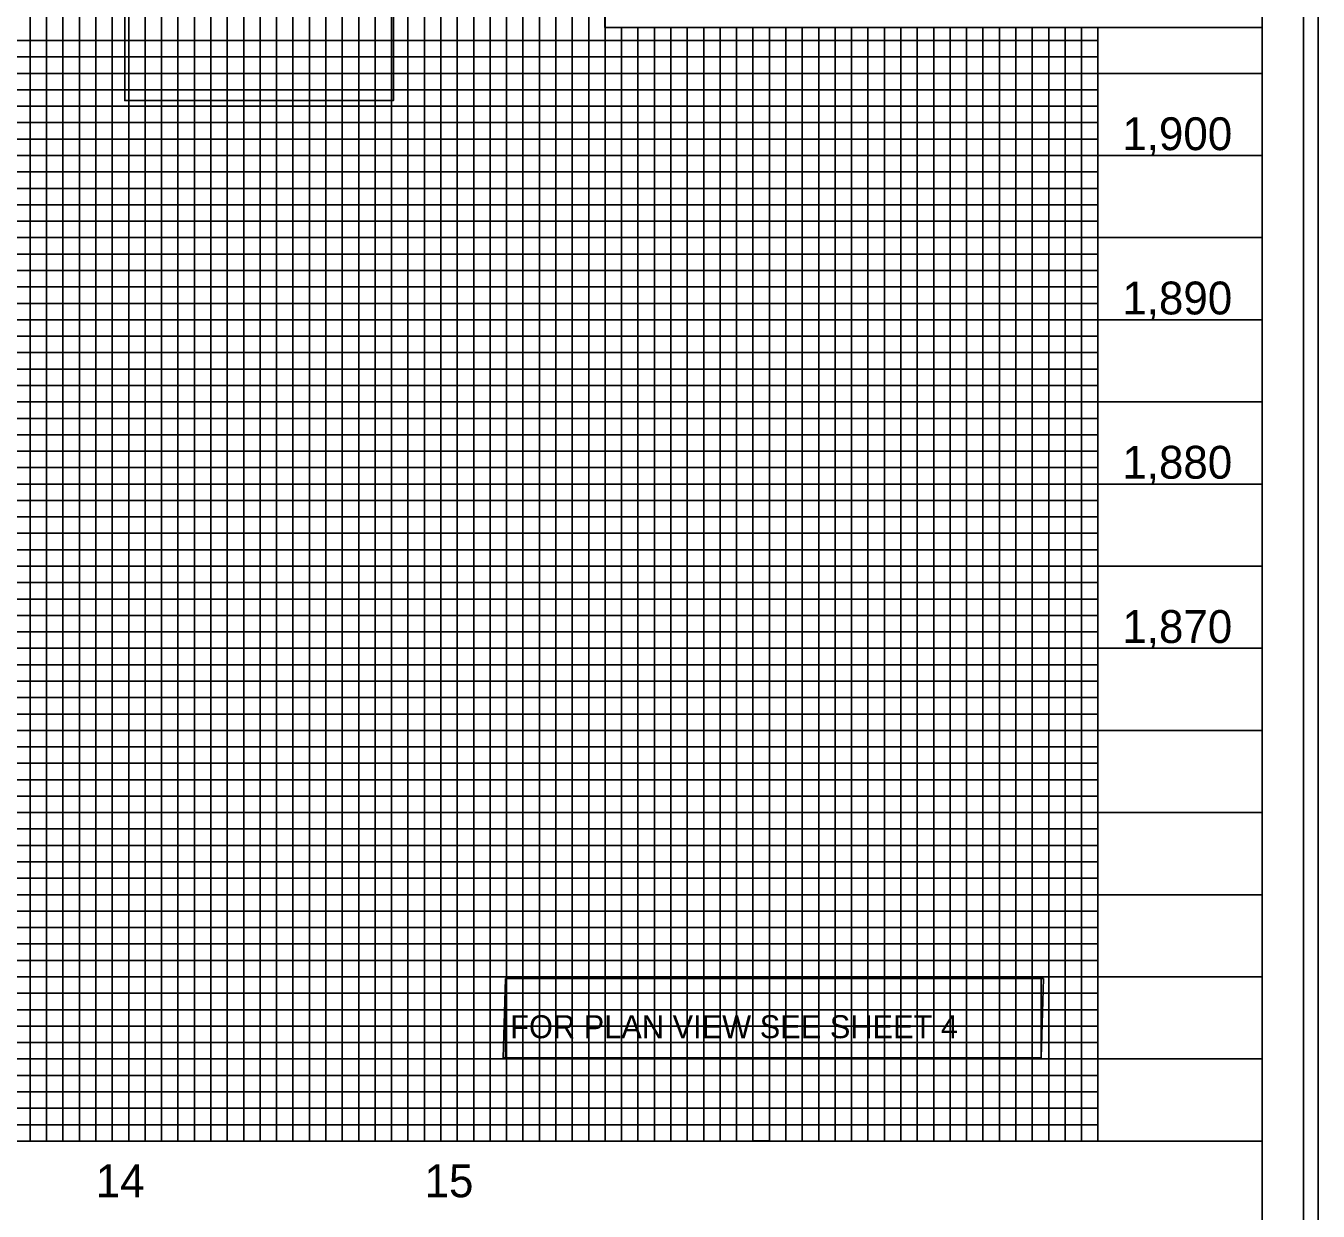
# Model space of a CAD drawing. Extents: x 557032 to 558840, y 515971 to 517218.
# Drawn here: x 558323.1 to 558716.5, y 516671.8 to 517032.6 of the extents above; entities that cross this region are included whole.
import ezdxf

# ---------------------------------------------------------------- set-up
doc = ezdxf.new("R2010")
doc.units = 0
for name, color, linetype in [('Exist Vertical Profile Horizontal Axis Label Major', 7, 'Continuous'), ('Exist Vertical Profile Vertical Axis Label', 7, 'Continuous'), ('Prop Vertical Profile Grade Label', 7, 'Continuous'), ('Prop VPI Label', 7, 'Continuous'), ('Scratch_Level_5', 7, 'Continuous'), ('Sheet DOT Grid CELL', 7, 'Continuous'), ('Sheet Layout Profile Border Port 1', 7, 'Continuous'), ('Sheet Plot Border Inside CELL', 7, 'Continuous'), ('Sheet Plot Border Outside CELL', 7, 'Continuous'), ('Sheet Profile CELL', 7, 'Continuous'), ('Sheet Profile Grid Major CELL', 7, 'Continuous'), ('Sheet Profile Grid Middle CELL', 7, 'Continuous'), ('Sheet Profile Grid Minor CELL', 7, 'Continuous'), ('Sheet Sticker Exception Certification CELL', 7, 'Continuous')]:
    doc.layers.add(name, color=color, linetype=linetype)

msp = doc.modelspace()

# ---------------------------------------------------------------- linework, layer by layer
at = {"layer": 'Prop Vertical Profile Grade Label'}
msp.add_lwpolyline([(558353.25, 517063.44), (558435.01, 517063.44), (558435.01, 517009.9), (558353.25, 517009.9)], close=True, dxfattribs=at)
at = {"layer": 'Prop VPI Label'}
for points in [[(558469.16, 516742.65), (558632.86, 516742.65), (558632.14, 516718.54), (558468.44, 516718.54)], [(558469.16, 516742.65), (558632.14, 516742.65), (558632.14, 516718.54), (558469.16, 516718.54)]]:
    msp.add_lwpolyline(points, close=True, dxfattribs=at)
at = {"layer": 'Scratch_Level_5'}
msp.add_lwpolyline([(558499.45, 517193.17), (558099.45, 517193.17), (558099.45, 516693.17), (558649.45, 516693.17), (558649.45, 517032.12), (558499.45, 517032.12)], close=True, dxfattribs=at)
at = {"layer": 'Sheet DOT Grid CELL'}
for p, q in [((558349.45, 516693.17), (558349.45, 517193.17)), ((558399.45, 516693.17), (558399.45, 517193.17)), ((558449.45, 516693.17), (558449.45, 517193.17)), ((558499.45, 516693.17), (558499.45, 517055.62)), ((558549.45, 516693.17), (558549.45, 517032.12)), ((558599.45, 516693.17), (558599.45, 517032.12)), ((558649.45, 516693.17), (558649.45, 517032.12)), ((558699.45, 516993.17), (557199.45, 516993.17)), ((558699.45, 516943.17), (557199.45, 516943.17)), ((558699.45, 516893.17), (557199.45, 516893.17)), ((558699.45, 516843.17), (557199.45, 516843.17)), ((558699.45, 516793.17), (557199.45, 516793.17)), ((558699.45, 516743.17), (557199.45, 516743.17))]:
    msp.add_line(p, q, dxfattribs=at)
at = {"layer": 'Sheet Layout Profile Border Port 1'}
msp.add_lwpolyline([(557249.45, 517032.12), (557249.45, 516693.17), (558649.45, 516693.17), (558649.45, 517032.12)], dxfattribs=at)
at = {"layer": 'Sheet Plot Border Inside CELL'}
msp.add_lwpolyline([(557045.45, 516140.62), (558711.95, 516140.62), (558711.95, 517195.72), (557045.45, 517195.72)], close=True, dxfattribs=at)
at = {"layer": 'Sheet Plot Border Outside CELL'}
msp.add_lwpolyline([(557032.45, 516118.17), (558716.45, 516118.17), (558716.45, 517218.17), (557032.45, 517218.17)], close=True, dxfattribs=at)
at = {"layer": 'Sheet Profile CELL'}
msp.add_line((557199.45, 516693.17), (558699.45, 516693.17), dxfattribs=at)
msp.add_lwpolyline([(558699.45, 517193.17), (557199.45, 517193.17), (557199.45, 516143.17), (558699.45, 516143.17)], close=True, dxfattribs=at)
at = {"layer": 'Sheet Profile Grid Major CELL'}
for points in [[(557999.45, 517193.17), (558049.45, 517193.17), (558049.45, 516842.99), (558099.45, 516842.99), (558099.45, 517193.17), (558149.45, 517193.17), (558149.45, 516693.17), (558199.45, 516693.17), (558199.45, 517193.17), (558249.45, 517193.17), (558249.45, 516693.17), (558299.45, 516693.17), (558299.45, 517193.17), (558349.45, 517193.17), (558349.45, 516693.17), (558399.45, 516693.17), (558399.45, 517193.17), (558449.45, 517193.17), (558449.45, 516693.17), (558499.45, 516693.17), (558499.45, 517193.17), (558525.75, 517193.17)], [(558649.45, 517032.12), (558649.45, 516693.17), (558699.45, 516693.17), (558699.45, 517043.17)], [(558549.45, 517032.12), (558549.45, 516693.17), (558599.45, 516693.17), (558599.45, 516693.17), (558599.45, 517032.12)], [(558699.45, 516993.17), (557199.45, 516993.17), (557199.45, 516943.17), (558699.45, 516943.17)], [(558699.45, 516893.17), (557199.45, 516893.17), (557199.45, 516843.17), (558699.45, 516843.17)], [(558699.45, 516793.17), (557199.45, 516793.17), (557199.45, 516793.17), (557199.45, 516743.17), (558699.45, 516743.17)]]:
    msp.add_lwpolyline(points, dxfattribs=at)
at = {"layer": 'Sheet Profile Grid Middle CELL'}
for points in [[(558024.45, 517193.17), (558074.45, 517193.17), (558074.45, 516693.17), (558124.45, 516693.17), (558124.45, 517193.17), (558174.45, 517193.17), (558174.45, 516693.17), (558224.45, 516693.17), (558224.45, 517193.17), (558274.45, 517193.17), (558274.45, 516693.17), (558324.45, 516693.17), (558324.45, 517193.17), (558374.45, 517193.17), (558374.45, 516693.17), (558424.45, 516693.17), (558424.45, 517193.17), (558474.45, 517193.17), (558474.45, 516693.17), (558524.45, 516693.17), (558524.45, 517032.12)], [(558524.45, 516955.97), (558524.45, 516693.17), (558574.45, 516693.17), (558574.45, 517032.12)], [(558574.45, 516955.97), (558574.45, 516693.17), (558624.45, 516693.17), (558624.45, 517032.12)], [(558699.45, 517018.17), (557199.45, 517018.17), (557199.45, 516968.17), (558524.45, 516968.17)], [(558524.45, 516968.17), (558699.45, 516968.17)], [(558699.45, 516918.17), (557199.45, 516918.17), (557199.45, 516868.17), (558699.45, 516868.17)], [(558699.45, 516818.17), (557199.45, 516818.17), (557199.45, 516768.17), (558699.45, 516768.17)], [(558699.45, 516718.17), (557199.45, 516718.17)]]:
    msp.add_lwpolyline(points, dxfattribs=at)
at = {"layer": 'Sheet Profile Grid Minor CELL'}
for p, q in [((557249.45, 517028.17), (558649.45, 517028.17)), ((558649.45, 517008.17), (557249.45, 517008.17)), ((557249.45, 517003.17), (558649.45, 517003.17)), ((558649.45, 516983.17), (557249.45, 516983.17)), ((557249.45, 516978.17), (558649.45, 516978.17)), ((558649.45, 516958.17), (557249.45, 516958.17)), ((557249.45, 516953.17), (558649.45, 516953.17)), ((558649.45, 516948.17), (557249.45, 516948.17)), ((557249.45, 516938.17), (558649.45, 516938.17)), ((558649.45, 516933.17), (557249.45, 516933.17)), ((557249.45, 516928.17), (558649.45, 516928.17)), ((558649.45, 516923.17), (557249.45, 516923.17)), ((557249.45, 516913.17), (558649.45, 516913.17)), ((558649.45, 516908.17), (557249.45, 516908.17)), ((557249.45, 516903.17), (558649.45, 516903.17)), ((558649.45, 516898.17), (557249.45, 516898.17)), ((557249.45, 516888.17), (558649.45, 516888.17)), ((558649.45, 516883.17), (557249.45, 516883.17)), ((557249.45, 516878.17), (558649.45, 516878.17)), ((558649.45, 516873.17), (557249.45, 516873.17)), ((557249.45, 516863.17), (558649.45, 516863.17)), ((558649.45, 516858.17), (557249.45, 516858.17)), ((557249.45, 516853.17), (558649.45, 516853.17)), ((558649.45, 516848.17), (557249.45, 516848.17)), ((557249.45, 516838.17), (558649.45, 516838.17)), ((558649.45, 516833.17), (557249.45, 516833.17)), ((557249.45, 516828.17), (558649.45, 516828.17)), ((558649.45, 516823.17), (557249.45, 516823.17)), ((557249.45, 516813.17), (558649.45, 516813.17)), ((558649.45, 516808.17), (557249.45, 516808.17)), ((558649.45, 516803.17), (557249.45, 516803.17)), ((558649.45, 516798.17), (557249.45, 516798.17)), ((557249.45, 516788.17), (558649.45, 516788.17)), ((558649.45, 516783.17), (557249.45, 516783.17)), ((557249.45, 516778.17), (558649.45, 516778.17)), ((558649.45, 516773.17), (557249.45, 516773.17)), ((557249.45, 516763.17), (558649.45, 516763.17)), ((558649.45, 516758.17), (557249.45, 516758.17)), ((557249.45, 516753.17), (558649.45, 516753.17)), ((558649.45, 516748.17), (557249.45, 516748.17)), ((557249.45, 516738.17), (558649.45, 516738.17)), ((558649.45, 516733.17), (557249.45, 516733.17)), ((557249.45, 516728.17), (558649.45, 516728.17)), ((558649.45, 516723.17), (557249.45, 516723.17)), ((557249.45, 516713.17), (558649.45, 516713.17)), ((558649.45, 516708.17), (557249.45, 516708.17)), ((557249.45, 516703.17), (558649.45, 516703.17))]:
    msp.add_line(p, q, dxfattribs=at)
for points in [[(558319.45, 517193.17), (558329.45, 517193.17), (558329.45, 516693.17), (558334.45, 516693.17), (558334.45, 517193.17), (558339.45, 517193.17), (558339.45, 516693.17), (558344.45, 516693.17), (558344.45, 517193.17), (558354.45, 517193.17), (558354.45, 516693.17), (558359.45, 516693.17), (558359.45, 517193.17), (558364.45, 517193.17), (558364.45, 516693.17), (558369.45, 516693.17), (558369.45, 517193.17), (558379.45, 517193.17), (558379.45, 516693.17), (558384.45, 516693.17), (558384.45, 517193.17), (558389.45, 517193.17), (558389.45, 516693.17)], [(558389.45, 516693.17), (558394.45, 516693.17), (558394.45, 517193.17)], [(558404.45, 517193.17), (558404.45, 516693.17), (558409.45, 516693.17), (558409.45, 517193.17)], [(558414.45, 517193.17), (558414.45, 516693.17), (558419.45, 516693.17), (558419.45, 517193.17)], [(558429.45, 517193.17), (558429.45, 516693.17), (558434.45, 516693.17), (558434.45, 517193.17)], [(558439.45, 517193.17), (558439.45, 516693.17), (558444.45, 516693.17), (558444.45, 517193.17)], [(558454.45, 517193.17), (558454.45, 516693.17), (558459.45, 516693.17), (558459.45, 517193.17)], [(558464.45, 517193.17), (558464.45, 516693.17), (558469.45, 516693.17), (558469.45, 517193.17)], [(558479.45, 517193.17), (558479.45, 516693.17), (558484.45, 516693.17), (558484.45, 517193.17)], [(558489.45, 517193.17), (558489.45, 516693.17), (558494.45, 516693.17), (558494.45, 517193.17)], [(558504.45, 517032.12), (558504.45, 516693.17), (558509.45, 516693.17), (558509.45, 517032.12)], [(558514.45, 517032.12), (558514.45, 516693.17), (558519.45, 516693.17), (558519.45, 517032.12)], [(558529.45, 517032.12), (558529.45, 516693.17), (558529.45, 516693.17), (558534.45, 516693.17), (558539.45, 516693.17), (558539.45, 517032.12)], [(558534.45, 517032.12), (558534.45, 516693.17)], [(558544.45, 517032.12), (558544.35, 516693.22), (558549.35, 516693.22), (558554.45, 516693.17), (558554.45, 517032.12)], [(558554.45, 516955.97), (558554.45, 516693.17), (558559.45, 516693.17), (558559.45, 517032.12)], [(558564.45, 517032.12), (558564.45, 516693.17), (558569.45, 516693.17), (558569.45, 517032.12)], [(558579.45, 517032.12), (558579.45, 516693.17), (558584.45, 516693.17), (558584.45, 517032.12)], [(558589.45, 517032.12), (558589.45, 516693.17), (558594.45, 516693.17), (558594.45, 517032.12)], [(558604.45, 517032.12), (558604.45, 516693.17), (558609.45, 516693.17), (558609.45, 517032.12)], [(558614.45, 517032.12), (558614.45, 516693.17), (558619.45, 516693.17), (558619.45, 517032.12)], [(558629.45, 517032.12), (558629.45, 516693.17), (558634.45, 516693.17), (558634.45, 517032.12)], [(558639.45, 517032.12), (558639.45, 516693.17), (558644.45, 516693.17), (558644.45, 517032.12)], [(558649.45, 517023.17), (557249.45, 517023.17), (557249.45, 517013.17), (558649.45, 517013.17)], [(558649.45, 516998.17), (557249.45, 516998.17), (557249.45, 516988.17), (558649.45, 516988.17)], [(558649.45, 516973.17), (557249.45, 516973.17), (557249.45, 516963.17), (558649.45, 516963.17)], [(558649.45, 516698.17), (557249.45, 516698.17)]]:
    msp.add_lwpolyline(points, dxfattribs=at)
at = {"layer": 'Sheet Sticker Exception Certification CELL'}
for p, q in [((558499.4, 517032.12), (558499.4, 517055.62)), ((558499.4, 517032.12), (558499.4, 517055.62)), ((558699.44, 517055.6), (558699.44, 517032.1)), ((558699.44, 517055.6), (558699.44, 517032.1)), ((558699.44, 517032.12), (558499.4, 517032.12)), ((558699.44, 517032.12), (558499.4, 517032.12))]:
    msp.add_line(p, q, dxfattribs=at)

# ---------------------------------------------------------------- texts
at = {"layer": 'Exist Vertical Profile Horizontal Axis Label Major'}
for s, p in [('14', (558344.41, 516676.08)), ('15', (558444.49, 516676.08))]:
    msp.add_text(s, height=10, dxfattribs=at).set_placement(p)
at = {"layer": 'Exist Vertical Profile Vertical Axis Label'}
for s, p in [('1,900', (558656.84, 516994.8)), ('1,900', (558656.84, 516994.8)), ('1,890', (558656.84, 516944.8)), ('1,890', (558656.84, 516944.8)), ('1,880', (558656.84, 516894.8)), ('1,880', (558656.84, 516894.8)), ('1,870', (558656.84, 516844.8)), ('1,870', (558656.84, 516844.8))]:
    msp.add_text(s, height=10, dxfattribs=at).set_placement(p)
at = {"layer": 'Prop VPI Label'}
msp.add_text('FOR PLAN VIEW SEE SHEET 4', height=7, dxfattribs=at).set_placement((558470.56, 516724.49))

doc.saveas('drawing.dxf')
